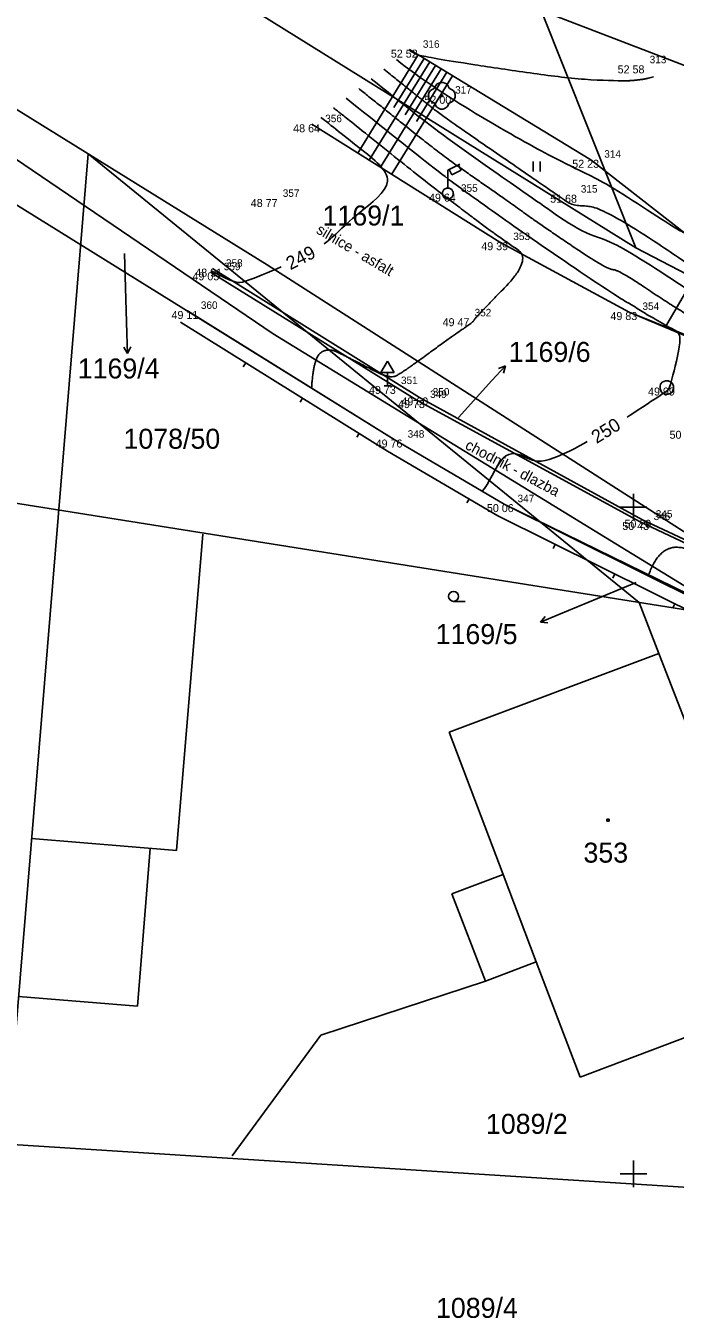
# Model space of a CAD drawing. Extents: x -704057 to -703795, y -1008732 to -1008584.
# Drawn here: x -704022.78 to -703998.45, y -1008680.42 to -1008631.96 of the extents above; entities that cross this region are included whole.
import ezdxf

# ---------------------------------------------------------------- set-up
doc = ezdxf.new("R2010")
doc.units = 0
for name, color, linetype in [('Z_body', 7, 'Continuous'), ('Z_body_cisla', 7, 'Continuous'), ('Z_body_vysky', 7, 'Continuous'), ('Z_dopravni_znaceni', 7, 'Continuous'), ('Z_hekt_sit', 7, 'Continuous'), ('Z_katastr_cisla_pozemkove', 7, 'Continuous'), ('Z_katastr_cisla_stavebni', 7, 'Continuous'), ('Z_katastr_hranice', 7, 'Continuous'), ('Z_katastr_hranice_KU', 7, 'Continuous'), ('Z_katastr_vnitrni_kresba', 7, 'Continuous'), ('Z_katastr_znacky', 7, 'Continuous'), ('Z_komunikace_zpevn_pl', 7, 'Continuous'), ('Z_obruby', 7, 'Continuous'), ('Z_oploceni', 7, 'Continuous'), ('Z_popis', 7, 'Continuous'), ('Z_site_znaky_kanalizace', 7, 'Continuous'), ('Z_site_znaky_VO', 7, 'Continuous'), ('Z_teren_hrany_paty', 7, 'Continuous'), ('Z_vrstevnice_popis', 7, 'Continuous'), ('Z_vrstevnice_vedlejsi', 7, 'Continuous'), ('Z_zelen_jednotliva', 7, 'Continuous')]:
    doc.layers.add(name, color=color, linetype=linetype)

# ---------------------------------------------------------------- blocks, each defined once
blk = doc.blocks.new('POINT_DISPLAY')
blk.add_line((0, 0), (0, 0))
blk = doc.blocks.new('Z210')
blk.add_line((0, 0), (0, 0.17))
blk = doc.blocks.new('Z24')
for p, q in [((-0.17, 0.45), (-0.05, 0.5)), ((-0.05, 0.5), (0.05, 0.5)), ((0.05, 0.5), (0.17, 0.45)), ((-0.5, 0.05), (-0.47, 0.13)), ((-0.5, -0.05), (-0.5, 0.05)), ((-0.47, 0.13), (-0.42, 0.2)), ((-0.42, 0.2), (-0.28, 0.28)), ((-0.28, 0.28), (-0.23, 0.38)), ((-0.23, 0.38), (-0.17, 0.45)), ((-0.03, -0.03), (-0.03, 0.03)), ((-0.03, 0.03), (0.03, 0.03)), ((0.03, 0.03), (0.03, -0.03)), ((0.17, 0.45), (0.23, 0.38)), ((0.23, 0.38), (0.28, 0.28)), ((0.28, 0.28), (0.42, 0.2)), ((0.42, 0.2), (0.47, 0.13)), ((0.47, 0.13), (0.5, 0.05)), ((0.5, 0.05), (0.5, -0.05)), ((-0.45, -0.17), (-0.5, -0.05)), ((-0.38, -0.23), (-0.45, -0.17)), ((-0.28, -0.28), (-0.38, -0.23)), ((-0.2, -0.42), (-0.28, -0.28)), ((-0.13, -0.47), (-0.2, -0.42)), ((-0.05, -0.5), (-0.13, -0.47)), ((0.03, -0.03), (-0.03, -0.03)), ((0.13, -0.47), (0.05, -0.5)), ((0.2, -0.42), (0.13, -0.47)), ((0.28, -0.28), (0.2, -0.42)), ((0.38, -0.23), (0.28, -0.28)), ((0.45, -0.17), (0.38, -0.23)), ((0.5, -0.05), (0.45, -0.17)), ((0.05, -0.5), (-0.05, -0.5))]:
    blk.add_line(p, q)
blk = doc.blocks.new('Z13')
for p, q in [((0, 0.88), (0.45, 1.1)), ((0.4, 1.07), (0.5, 0.88)), ((0, 0.2), (0, 0.88)), ((0.15, 0.7), (0.05, 0.9)), ((0.5, 0.88), (0.15, 0.7)), ((-0.2, 0.05), (-0.15, 0.15)), ((-0.2, -0.05), (-0.2, 0.05)), ((-0.15, 0.15), (-0.05, 0.2)), ((-0.05, 0.2), (0.05, 0.2)), ((0.05, 0.2), (0.15, 0.15)), ((0.15, 0.15), (0.2, 0.05)), ((0.2, 0.05), (0.2, -0.05)), ((-0.15, -0.15), (-0.2, -0.05)), ((-0.05, -0.2), (-0.15, -0.15)), ((0.05, -0.2), (-0.05, -0.2)), ((0.15, -0.15), (0.05, -0.2)), ((0.2, -0.05), (0.15, -0.15))]:
    blk.add_line(p, q)
blk = doc.blocks.new('Z620')
for p, q in [((-0.25, 0.05), (-0.23, 0.13)), ((-0.25, -0.05), (-0.25, 0.05)), ((-0.23, 0.13), (-0.17, 0.2)), ((-0.17, 0.2), (-0.05, 0.25)), ((-0.05, 0.25), (0.05, 0.25)), ((0.05, 0.25), (0.17, 0.2)), ((0.17, 0.2), (0.23, 0.13)), ((0.23, 0.13), (0.25, 0.05)), ((0.25, 0.05), (0.25, -0.05)), ((-0.2, -0.17), (-0.25, -0.05)), ((-0.13, -0.23), (-0.2, -0.17)), ((-0.05, -0.25), (-0.13, -0.23)), ((0.05, -0.25), (-0.05, -0.25)), ((0.13, -0.23), (0.05, -0.25)), ((0.2, -0.17), (0.13, -0.23)), ((0.25, -0.05), (0.2, -0.17))]:
    blk.add_line(p, q)
blk = doc.blocks.new('Z527')
for p, q in [((0, 0.93), (-0.25, 0.5)), ((-0.25, 0.5), (0.25, 0.5)), ((0.25, 0.5), (0, 0.93)), ((0, 0), (0, 0.5)), ((-0.13, 0), (0.13, 0))]:
    blk.add_line(p, q)
blk = doc.blocks.new('Z402')
for p, q in [((-0.03, 0.03), (0.05, 0.03)), ((-0.03, -0.05), (-0.03, 0.03)), ((0.05, 0.03), (0.05, -0.05)), ((0.05, -0.05), (-0.03, -0.05))]:
    blk.add_line(p, q)
blk = doc.blocks.new('Z61')
for p, q in [((0, 0.75), (-0.13, 0.5)), ((0, 0), (0, 0.75)), ((0, 0.75), (0.13, 0.5))]:
    blk.add_line(p, q)
blk = doc.blocks.new('Z306')
for p, q in [((-0.13, 0.17), (-0.13, -0.2)), ((0.13, 0.17), (0.13, -0.2))]:
    blk.add_line(p, q)
blk = doc.blocks.new('Z304')
blk.add_line((0, -0.19), (0.44, -0.19))
blk.add_circle((0, 0), 0.188)

msp = doc.modelspace()

# ---------------------------------------------------------------- linework, layer by layer
at = {"layer": 'Z_hekt_sit'}
for p, q in [((-704000, -1008649.5), (-704000, -1008650.5)), ((-704000.5, -1008650), (-703999.5, -1008650)), ((-704000, -1008674.5), (-704000, -1008675.5)), ((-704000.5, -1008675), (-703999.5, -1008675))]:
    msp.add_line(p, q, dxfattribs=at)
at = {"layer": 'Z_katastr_cisla_pozemkove'}
for points in [[(-704019.08, -1008640.49), (-704018.99, -1008643.5)], [(-704006.57, -1008646.64), (-704005.31, -1008645.26)], [(-703999.91, -1008652.83), (-704002.8, -1008654.03)]]:
    msp.add_lwpolyline(points, dxfattribs=at)
at = {"layer": 'Z_katastr_hranice'}
for p, q in [((-703999.92, -1008640.28), (-704025.1, -1008624.6)), ((-704013.74, -1008640.92), (-704024.4, -1008634.31)), ((-704023.51, -1008673.88), (-704020.45, -1008636.76)), ((-704020.45, -1008636.76), (-703999.79, -1008653.58)), ((-704008.97, -1008647.47), (-704023.19, -1008638.63)), ((-703996.49, -1008651.97), (-704013.74, -1008640.92)), ((-704004.85, -1008649.89), (-704008.97, -1008647.47)), ((-703996.14, -1008654.16), (-704025.87, -1008649.43)), ((-703996.14, -1008654.16), (-704004.85, -1008649.89)), ((-703999.05, -1008655.49), (-703999.79, -1008653.58)), ((-703994.08, -1008668.38), (-703999.05, -1008655.49)), ((-704005.55, -1008667.78), (-704003.65, -1008667.06)), ((-704002.01, -1008671.38), (-704003.65, -1008667.06)), ((-704005.55, -1008667.78), (-704011.72, -1008669.8)), ((-703994.08, -1008668.38), (-704002.01, -1008671.38)), ((-704011.72, -1008669.8), (-704015.05, -1008674.33)), ((-703987.75, -1008676.17), (-704026.16, -1008673.72))]:
    msp.add_line(p, q, dxfattribs=at)
at = {"layer": 'Z_katastr_hranice_KU'}
for p, q in [((-704003.46, -1008631.38), (-703999.92, -1008640.28)), ((-703999.92, -1008640.28), (-703993.4, -1008643.68))]:
    msp.add_line(p, q, dxfattribs=at)
at = {"layer": 'Z_katastr_vnitrni_kresba'}
for p, q in [((-704003.46, -1008631.38), (-703996.18, -1008634.19)), ((-704013.51, -1008643.51), (-704024.13, -1008636.3)), ((-703996.14, -1008654.16), (-704013.51, -1008643.51)), ((-704016.15, -1008651.02), (-704017.13, -1008662.88)), ((-703999.05, -1008655.49), (-704006.91, -1008658.44)), ((-704004.89, -1008663.78), (-704006.91, -1008658.44)), ((-704017.13, -1008662.88), (-704022.57, -1008662.43)), ((-704018.6, -1008668.72), (-704018.12, -1008662.8)), ((-704006.81, -1008664.5), (-704004.89, -1008663.78)), ((-704003.65, -1008667.06), (-704004.89, -1008663.78)), ((-704005.55, -1008667.78), (-704006.81, -1008664.5)), ((-704018.6, -1008668.72), (-704023.05, -1008668.35))]:
    msp.add_line(p, q, dxfattribs=at)
at = {"layer": 'Z_komunikace_zpevn_pl'}
for p, q in [((-704012.06, -1008635.65), (-704005.01, -1008640.07)), ((-704005.01, -1008640.07), (-704000.17, -1008642.69)), ((-704015.78, -1008641.06), (-704008.03, -1008645.89)), ((-704000.17, -1008642.69), (-703993.53, -1008645.49)), ((-703999.67, -1008650.48), (-704008.03, -1008645.89)), ((-703999.67, -1008650.48), (-703996.49, -1008651.97))]:
    msp.add_line(p, q, dxfattribs=at)
at = {"layer": 'Z_obruby'}
for p, q in [((-704008.13, -1008645.99), (-704015.86, -1008641.2)), ((-703999.75, -1008650.56), (-704008.13, -1008645.99)), ((-703996.54, -1008652.07), (-703999.75, -1008650.56))]:
    msp.add_line(p, q, dxfattribs=at)
at = {"layer": 'Z_oploceni'}
for p, q in [((-704008.97, -1008647.47), (-704016.72, -1008642.65)), ((-704009.23, -1008647.9), (-704016.98, -1008643.07)), ((-704004.85, -1008649.89), (-704008.97, -1008647.47)), ((-704005.09, -1008650.33), (-704009.23, -1008647.9)), ((-703997.12, -1008653.74), (-704004.85, -1008649.89)), ((-703997.34, -1008654.19), (-704005.09, -1008650.33))]:
    msp.add_line(p, q, dxfattribs=at)
at = {"layer": 'Z_teren_hrany_paty'}
for p, q in [((-704008.07, -1008633.05), (-704010.34, -1008636.73)), ((-704007.85, -1008633.18), (-704008.99, -1008635.02)), ((-704001.6, -1008636.98), (-704008.4, -1008632.85)), ((-704007.64, -1008633.31), (-704009.91, -1008637)), ((-704007.21, -1008633.57), (-704009.49, -1008637.26)), ((-704007.43, -1008633.44), (-704008.56, -1008635.29)), ((-704007, -1008633.7), (-704008.14, -1008635.55)), ((-704006.79, -1008633.83), (-704009.07, -1008637.53)), ((-703994.94, -1008642.2), (-704001.6, -1008636.98)), ((-703997.18, -1008640.44), (-703998.81, -1008643.24)), ((-704000.17, -1008642.69), (-703994.34, -1008645.06))]:
    msp.add_line(p, q, dxfattribs=at)
at = {"layer": 'Z_vrstevnice_popis'}
for points in [[(-704008.891, -1008633.225), (-704007.19, -1008634.58), (-704001.968, -1008637.528), (-704001.463, -1008637.527), (-703997.448, -1008640.245), (-703998.103, -1008639.589), (-703997.814, -1008638.926)], [(-704009.834, -1008633.947), (-704008.639, -1008634.898), (-704007.097, -1008636.135), (-704003.977, -1008638.277), (-704003.231, -1008638.819), (-704001.631, -1008639.907), (-704000.867, -1008639.906), (-703997.17, -1008642.409), (-703994.823, -1008643.756), (-703994.703, -1008643.728), (-703993.348, -1008643.651), (-703992.995, -1008642.406), (-703992.399, -1008642.624), (-703992.166, -1008642.575), (-703991.675, -1008642.426), (-703991.193, -1008642.529), (-703990.961, -1008642.637)], [(-704010.777, -1008634.669), (-704010.089, -1008635.217), (-704007.004, -1008637.69), (-704006.178, -1008638.257), (-704004.336, -1008639.596), (-704000.382, -1008642.286), (-704000.271, -1008642.286), (-703999.734, -1008642.649), (-703999.257, -1008642.923), (-703998.4, -1008643.409), (-703998.154, -1008643.54), (-703998.629, -1008645.519), (-703998.717, -1008645.615), (-703998.773, -1008645.668), (-703999.967, -1008646.451), (-704000.248, -1008646.631)], [(-704011.72, -1008635.39), (-704011.538, -1008635.535), (-704010.228, -1008636.586), (-704008.676, -1008637.772), (-704010.445, -1008639.051), (-704011.109, -1008639.735), (-704011.481, -1008640.045), (-704011.596, -1008640.129)], [(-704013.213, -1008640.994), (-704013.639, -1008641.186), (-704014.804, -1008641.672), (-704014.94, -1008641.601), (-704015.831, -1008641.15)], [(-704001.738, -1008647.549), (-704002.051, -1008647.729), (-704003.388, -1008648.453), (-704004.04, -1008648.141), (-704004.898, -1008647.753), (-704005.446, -1008649.181), (-704005.674, -1008649.406)]]:
    msp.add_open_spline(points, degree=3, dxfattribs=at)
at = {"layer": 'Z_vrstevnice_vedlejsi'}
for points in [[(-704008.419, -1008632.864), (-704008.353, -1008632.917), (-704007.931, -1008633.135), (-704000.289, -1008634.249), (-703999.256, -1008633.864)], [(-704009.362, -1008633.586), (-704007.915, -1008634.739), (-704007.143, -1008635.358), (-704002.876, -1008638.286), (-704002.679, -1008638.43), (-704002.255, -1008638.718), (-704001.165, -1008638.717), (-703995.889, -1008642.289), (-703994.89, -1008642.862), (-703994.417, -1008642.752), (-703993.832, -1008642.719), (-703993.258, -1008640.696), (-703993.341, -1008639.701), (-703993.272, -1008639.432), (-703993.04, -1008638.835), (-703992.99, -1008638.745), (-703990.403, -1008638.423), (-703989.481, -1008638.539), (-703989.058, -1008638.588), (-703989.018, -1008638.516), (-703988.578, -1008638.54), (-703988.475, -1008638.554), (-703988.362, -1008638.685), (-703988.319, -1008638.754), (-703988.294, -1008638.815), (-703986.637, -1008641.391), (-703986.518, -1008641.581), (-703985.267, -1008643.657), (-703984.422, -1008644.955), (-703982.223, -1008646.72), (-703982.083, -1008646.9), (-703980.47, -1008647.779), (-703979.335, -1008647.914), (-703971.793, -1008648.878), (-703969.312, -1008649.063), (-703968.076, -1008649.117), (-703960.948, -1008649.919), (-703959.282, -1008650.186), (-703958.493, -1008650.28), (-703957.367, -1008650.455), (-703955.116, -1008650.684), (-703950.816, -1008651.182), (-703948.3, -1008651.463), (-703946.953, -1008651.576), (-703945.397, -1008651.505), (-703943.023, -1008651.703), (-703939.161, -1008651.987), (-703938.27, -1008652.079), (-703937.191, -1008652.194), (-703934.147, -1008651.524), (-703931.028, -1008650.815), (-703930.717, -1008650.764), (-703928.94, -1008650.83), (-703928.501, -1008650.751), (-703928.424, -1008650.713), (-703928.413, -1008650.708), (-703928.266, -1008650.724), (-703926.027, -1008648.737), (-703920.5, -1008648.624), (-703915.824, -1008649.925), (-703908.88, -1008649.843), (-703904.651, -1008650.155), (-703897.103, -1008651.333), (-703893.743, -1008651.997), (-703889.99, -1008652.252), (-703881.693, -1008653.228), (-703874.656, -1008652.961), (-703868.448, -1008652.365), (-703859.857, -1008652.906), (-703856.36, -1008653.001), (-703843.765, -1008653.766), (-703842.17, -1008653.801), (-703841.143, -1008653.824), (-703831.904, -1008654.28)], [(-704010.305, -1008634.308), (-704009.364, -1008635.058), (-704007.05, -1008636.913), (-704005.077, -1008638.267), (-704003.784, -1008639.207), (-704001.007, -1008641.096), (-704000.569, -1008641.096), (-703998.452, -1008642.529), (-703996.572, -1008643.608), (-703994.455, -1008644.81), (-703993.69, -1008644.725), (-703993.267, -1008644.95), (-703992.917, -1008644.879), (-703992.134, -1008645.881), (-703992.595, -1008646.639), (-703993.503, -1008647.958), (-703993.68, -1008648.547), (-703995.276, -1008650.526), (-703996.236, -1008651.302), (-703996.767, -1008651.84), (-703996.931, -1008651.871), (-703997.503, -1008651.617), (-703999.042, -1008651.416), (-703999.451, -1008652.579)], [(-704011.249, -1008635.029), (-704010.814, -1008635.376), (-704007.683, -1008637.886), (-704005.872, -1008639.269), (-704004.888, -1008639.984), (-704003.8, -1008640.725), (-704005.936, -1008642.901), (-704006.016, -1008643.07), (-704006.822, -1008643.605), (-704008.707, -1008644.994), (-704009.153, -1008645.19), (-704010.276, -1008644.607), (-704010.745, -1008644.37), (-704011.466, -1008644.019), (-704012.002, -1008644.418), (-704012.07, -1008645.542)]]:
    msp.add_open_spline(points, degree=2, dxfattribs=at)

# ---------------------------------------------------------------- block references
at = {"layer": 'Z_body'}
for p in [(-704008.4, -1008632.85), (-703999.9, -1008633.44), (-704007.19, -1008634.58), (-704012.06, -1008635.65), (-704001.6, -1008636.98), (-704013.65, -1008638.45), (-704006.97, -1008638.25), (-704002.48, -1008638.29), (-704005.01, -1008640.07), (-704015.86, -1008641.2), (-704015.78, -1008641.06), (-704016.72, -1008642.65), (-704006.46, -1008642.92), (-704000.17, -1008642.69), (-704009.22, -1008645.46), (-703998.76, -1008645.52), (-704008.13, -1008645.99), (-704008.03, -1008645.89), (-704008.97, -1008647.47), (-704004.85, -1008649.89), (-703999.75, -1008650.56), (-703999.67, -1008650.48)]:
    msp.add_blockref('POINT_DISPLAY', p, dxfattribs=at)
at = {"layer": 'Z_dopravni_znaceni'}
msp.add_blockref('Z527', (-704009.22, -1008645.46), dxfattribs=at)
at = {"layer": 'Z_katastr_cisla_pozemkove'}
for p, rotation in [((-704018.99, -1008643.5), -178.26430000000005), ((-704005.31, -1008645.26), -42.35750000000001), ((-704002.8, -1008654.03), 112.4259)]:
    msp.add_blockref('Z61', p, dxfattribs=dict(at, rotation=rotation))
at = {"layer": 'Z_katastr_znacky'}
msp.add_blockref('Z402', (-704000.97, -1008661.73), dxfattribs=at)
at = {"layer": 'Z_oploceni'}
for p, rotation in [((-704014.54, -1008644.6), 148.1), ((-704012.41, -1008645.92), 148.1), ((-704010.29, -1008647.24), 148.1), ((-704006.17, -1008649.7), 149.6), ((-704002.94, -1008651.4), 153.5), ((-704000.7, -1008652.51), 153.5), ((-703998.46, -1008653.63), 153.5)]:
    msp.add_blockref('Z210', p, dxfattribs=dict(at, rotation=rotation))
at = {"layer": 'Z_popis'}
for name, p in [('Z306', (-704003.63, -1008637.22)), ('Z304', (-704006.75, -1008653.35))]:
    msp.add_blockref(name, p, dxfattribs=at)
at = {"layer": 'Z_site_znaky_kanalizace'}
msp.add_blockref('Z620', (-703998.76, -1008645.52), dxfattribs=at)
at = {"layer": 'Z_site_znaky_VO'}
msp.add_blockref('Z13', (-704006.97, -1008638.25), dxfattribs=at)
at = {"layer": 'Z_zelen_jednotliva'}
msp.add_blockref('Z24', (-704007.19, -1008634.58), dxfattribs=at)

# ---------------------------------------------------------------- texts
at = {"layer": 'Z_body_cisla'}
for s, p in [('316', (-704007.9, -1008632.78)), ('313', (-703999.4, -1008633.36)), ('317', (-704006.69, -1008634.5)), ('356', (-704011.56, -1008635.57)), ('314', (-704001.1, -1008636.9)), ('357', (-704013.15, -1008638.37)), ('355', (-704006.47, -1008638.18)), ('315', (-704001.98, -1008638.21)), ('353', (-704004.51, -1008639.99)), ('359', (-704015.36, -1008641.12)), ('358', (-704015.28, -1008640.99)), ('360', (-704016.22, -1008642.57)), ('354', (-703999.67, -1008642.61)), ('352', (-704005.96, -1008642.85)), ('351', (-704008.72, -1008645.39)), ('349', (-704007.63, -1008645.91)), ('350', (-704007.53, -1008645.82)), ('348', (-704008.47, -1008647.4)), ('347', (-704004.35, -1008649.82)), ('346', (-703999.25, -1008650.49)), ('345', (-703999.17, -1008650.4))]:
    msp.add_text(s, height=0.28, dxfattribs=at).set_placement(p)
at = {"layer": 'Z_body_vysky'}
for s, p in [('52 52', (-704009.1, -1008633.15)), ('52 58', (-704000.6, -1008633.74)), ('52 00', (-704007.84, -1008634.88)), ('48 64', (-704012.76, -1008635.95)), ('52 23', (-704002.3, -1008637.28)), ('48 77', (-704014.35, -1008638.75)), ('49 64', (-704007.67, -1008638.55)), ('51 68', (-704003.13, -1008638.59)), ('49 39', (-704005.71, -1008640.37)), ('49 05', (-704016.535, -1008641.5)), ('48 91', (-704016.43, -1008641.36)), ('49 11', (-704017.32, -1008642.95)), ('49 47', (-704007.16, -1008643.22)), ('49 83', (-704000.87, -1008642.99)), ('49 73', (-704009.92, -1008645.76)), ('49 99', (-703999.46, -1008645.82)), ('49 73', (-704008.83, -1008646.29)), ('49 60', (-704008.705, -1008646.19)), ('50 16', (-703998.655, -1008647.44)), ('49 76', (-704009.67, -1008647.77)), ('50 06', (-704005.5, -1008650.19)), ('50 43', (-704000.425, -1008650.86)), ('50 29', (-704000.345, -1008650.78))]:
    msp.add_text(s, height=0.3, dxfattribs=at).set_placement(p)
at = {"layer": 'Z_katastr_cisla_pozemkove'}
for s, p in [('1169/1', (-704011.66, -1008639.445)), ('1169/6', (-704004.68, -1008644.56)), ('1169/4', (-704020.835, -1008645.18)), ('1078/50', (-704019.12, -1008647.815)), ('1169/5', (-704007.42, -1008655.14)), ('1089/2', (-704005.537, -1008673.505)), ('1089/4', (-704007.408, -1008680.405))]:
    msp.add_text(s, height=0.75, dxfattribs=at).set_placement(p)
at = {"layer": 'Z_katastr_cisla_stavebni'}
msp.add_text('353', height=0.75, dxfattribs=at).set_placement((-704001.88, -1008663.335))
at = {"layer": 'Z_popis'}
for s, rotation, p in [('silnice - asfalt', 329.4, (-704011.93, -1008639.71)), ('chodnik - dlazba', 332.1, (-704006.35, -1008647.8))]:
    msp.add_text(s, height=0.4, rotation=rotation, dxfattribs=at).set_placement(p)
at = {"layer": 'Z_vrstevnice_popis'}
for s, rotation, p in [('249', 27.0759, (-704012.865, -1008641.125)), ('250', 31.7249, (-704001.388, -1008647.64))]:
    msp.add_text(s, height=0.5, rotation=rotation, dxfattribs=at).set_placement(p)

doc.saveas('drawing.dxf')
